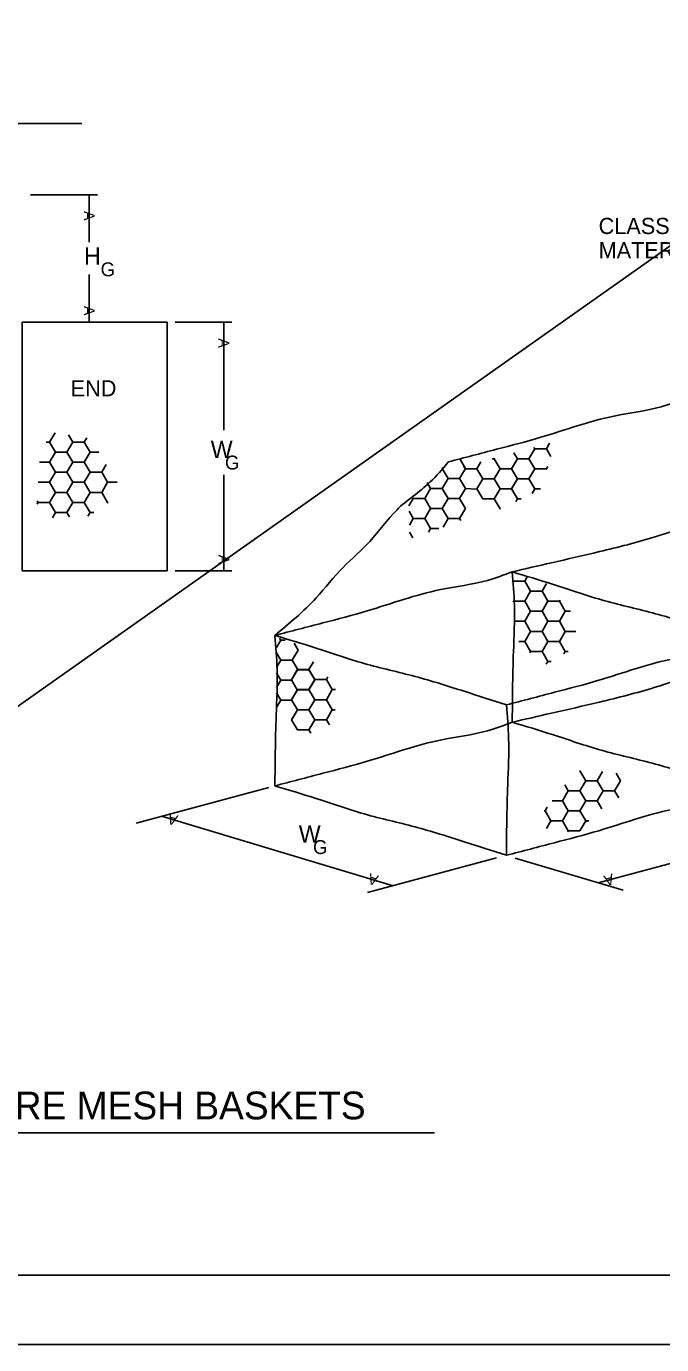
# Model space of a CAD drawing. Extents: x 3 to 3592, y -602 to 1171.
# Drawn here: x 2885 to 3022.2, y -601.8 to -317 of the extents above; entities that cross this region are included whole.
import ezdxf

# ---------------------------------------------------------------- set-up
doc = ezdxf.new("R2010")
doc.units = 0
for name, color, linetype in [('1', 7, 'Continuous'), ('2', 7, 'Continuous'), ('3', 7, 'Continuous')]:
    doc.layers.add(name, color=color, linetype=linetype)

msp = doc.modelspace()

# ---------------------------------------------------------------- linework, layer by layer
at = {"layer": '1'}
msp.add_line((2687.88, -601.81), (3528.88, -7.81), dxfattribs=at)
msp.add_lwpolyline([(2687.88, -7.81), (3528.88, -7.81), (3528.88, -601.81), (2687.88, -601.81)], close=True, dxfattribs=at)
msp.add_lwpolyline([(3512.88, -586.81), (3512.88, -22.81), (2726.88, -22.81), (2726.88, -586.81), (3512.88, -586.81), (3512.88, -560.45), (3312.88, -560.45), (3312.88, -495.77), (3512.88, -495.77), (3512.88, -466.81), (3312.88, -466.81), (3312.88, -586.81), (3391.68, -586.81), (3391.68, -560.45), (3391.68, -586.81), (3468.68, -586.81), (3468.68, -560.45), (3468.68, -572.77), (3512.88, -572.77)], dxfattribs=at)
at = {"layer": '2'}
for p, q in [((2885.86, -353.38), (2900.32, -353.38)), ((2898.57, -353.38), (2898.57, -363.63)), ((2898.57, -370.63), (2898.57, -380.88)), ((2913.61, -380.88), (2896.82, -380.88)), ((2917.11, -380.88), (2929.38, -380.88)), ((2927.63, -380.88), (2927.63, -404.26)), ((2927.63, -413.85), (2927.63, -434.63)), ((2979.76, -416.85), (2982.3, -416.95)), ((2917.11, -434.63), (2929.38, -434.63)), ((2989.96, -463.2), (2989.91, -467.34)), ((2937.38, -481.43), (2908.68, -489.13)), ((3069.4, -485.69), (3008.47, -502.03)), ((2948.9, -498.06), (2914.2, -487.65)), ((2964.2, -502.65), (2948.9, -498.06)), ((2986.53, -496.66), (2958.68, -504.13)), ((3013.87, -503.65), (2990.59, -496.67))]:
    msp.add_line(p, q, dxfattribs=at)
for points in [[(2915.36, -434.63), (2915.36, -380.88), (2884.11, -380.88), (2884.11, -434.63)], [(2893.75, -409.01), (2895, -406.84), (2897.5, -406.84), (2898.75, -409.01), (2897.5, -411.17), (2895, -411.17)], [(2890, -411.17), (2891.25, -409.01), (2893.75, -409.01), (2895, -411.17), (2893.75, -413.34), (2891.25, -413.34)], [(2893.75, -413.34), (2895, -411.17), (2897.5, -411.17), (2898.75, -413.34), (2897.5, -415.5), (2895, -415.5)], [(2986.05, -414.73), (2987.3, -412.57), (2989.8, -412.57), (2991.05, -414.73), (2989.8, -416.9), (2987.3, -416.9)], [(2989.8, -412.57), (2991.05, -410.4), (2993.55, -410.4), (2994.8, -412.57), (2993.55, -414.73), (2991.05, -414.73)], [(2890, -415.5), (2891.25, -413.34), (2893.75, -413.34), (2895, -415.5), (2893.75, -417.67), (2891.25, -417.67)], [(2893.75, -417.67), (2895, -415.5), (2897.5, -415.5), (2898.75, -417.67), (2897.5, -419.83), (2895, -419.83)], [(2897.5, -415.5), (2898.75, -413.34), (2901.25, -413.34), (2902.5, -415.5), (2901.25, -417.67), (2898.75, -417.67)], [(2974.81, -416.82), (2976.06, -414.65), (2978.56, -414.65), (2979.81, -416.82), (2978.56, -418.98), (2976.06, -418.98)], [(2982.3, -416.9), (2983.55, -414.73), (2986.05, -414.73), (2987.3, -416.9), (2986.05, -419.06), (2983.55, -419.06)], [(2890, -419.83), (2891.25, -417.67), (2893.75, -417.67), (2895, -419.83), (2893.75, -422), (2891.25, -422)], [(2992.64, -441.2), (2993.89, -439.04), (2996.39, -439.04), (2997.64, -441.2), (2996.39, -443.37), (2993.89, -443.37)], [(2992.64, -445.53), (2993.89, -443.37), (2996.39, -443.37), (2997.64, -445.53), (2996.39, -447.7), (2993.89, -447.7)], [(2996.39, -447.7), (2997.64, -445.53), (3000.14, -445.53), (3001.39, -447.7), (3000.14, -449.86), (2997.64, -449.86)], [(2942.26, -458.15), (2943.51, -455.99), (2946.01, -455.99), (2947.26, -458.15), (2946.01, -460.32), (2943.51, -460.32)], [(2942.28, -462.46), (2943.53, -460.29), (2946.03, -460.29), (2947.28, -462.46), (2946.03, -464.62), (2943.53, -464.62)], [(2942.28, -466.79), (2943.53, -464.62), (2946.03, -464.62), (2947.28, -466.79), (2946.03, -468.95), (2943.53, -468.95)], [(3004.55, -482.15), (3005.8, -479.98), (3008.3, -479.98), (3009.55, -482.15), (3008.3, -484.31), (3005.8, -484.31)], [(3000.79, -484.31), (3002.04, -482.15), (3004.54, -482.15), (3005.79, -484.31), (3004.54, -486.48), (3002.04, -486.48)]]:
    msp.add_lwpolyline(points, close=True, dxfattribs=at)
for points in [[(2889.25, -406.84), (2890, -406.84)], [(2890, -406.84), (2889.25, -406.84)], [(2891.17, -404.82), (2890, -406.84)], [(2890, -406.84), (2891.25, -409.01)], [(2895, -406.84), (2894.1, -405.27)], [(2897.5, -406.84), (2895, -406.84)], [(2898.06, -405.88), (2897.5, -406.84)], [(2998, -407.02), (2997.3, -408.24)], [(2997.3, -408.24), (2998, -407.02)], [(2891.25, -409.01), (2890, -411.17)], [(2897.5, -411.17), (2898.75, -409.01)], [(2898.75, -409.01), (2900.66, -409.01)], [(2991.05, -410.4), (2990.31, -409.12)], [(2990.31, -409.12), (2991.05, -410.4)], [(2994.8, -408.24), (2993.55, -410.4)], [(2993.55, -410.4), (2994.8, -408.24)], [(2994.63, -407.94), (2994.8, -408.24)], [(2994.8, -408.24), (2994.63, -407.94)], [(2994.8, -408.24), (2997.3, -408.24)], [(2997.3, -408.24), (2994.8, -408.24)], [(2997.3, -408.24), (2998.27, -409.92)], [(2998.27, -409.92), (2997.3, -408.24)], [(2890, -411.17), (2887.82, -411.17)], [(2887.82, -411.17), (2890, -411.17)], [(2890, -411.17), (2891.25, -413.34)], [(2898.75, -413.34), (2897.5, -411.17)], [(2902.24, -411.63), (2901.25, -413.34)], [(2901.25, -413.34), (2902.24, -411.63)], [(2974.73, -412.49), (2974.81, -412.49)], [(2974.81, -412.49), (2974.73, -412.49)], [(2974.91, -412.31), (2974.81, -412.49)], [(2974.81, -412.49), (2974.91, -412.31)], [(2974.81, -412.49), (2976.06, -414.65)], [(2976.06, -414.65), (2974.81, -412.49)], [(2979.81, -412.49), (2978.56, -414.65)], [(2978.61, -410.42), (2979.81, -412.49)], [(2979.8, -412.57), (2979.51, -412.07)], [(2982.3, -412.57), (2979.8, -412.57)], [(2983.16, -411.08), (2982.3, -412.57)], [(2982.3, -412.57), (2983.16, -411.08)], [(2983.55, -414.73), (2982.3, -412.57)], [(2986.05, -410.4), (2985.63, -410.4)], [(2985.63, -410.4), (2986.05, -410.4)], [(2986.13, -410.27), (2986.05, -410.4)], [(2986.05, -410.4), (2986.13, -410.27)], [(2987.3, -412.57), (2986.05, -410.4)], [(2986.05, -410.4), (2987.3, -412.57)], [(2987.3, -412.57), (2986.05, -414.73)], [(2989.8, -412.57), (2987.3, -412.57)], [(2991.05, -410.4), (2989.8, -412.57)], [(2993.55, -410.4), (2991.05, -410.4)], [(2994.8, -412.57), (2993.55, -410.4)], [(2993.55, -414.73), (2994.8, -412.57)], [(2997.3, -412.57), (2994.8, -412.57)], [(2994.8, -412.57), (2997.3, -412.57)], [(2997.59, -412.06), (2997.3, -412.57)], [(2997.3, -412.57), (2997.59, -412.06)], [(2997.38, -412.71), (2997.3, -412.57)], [(2997.3, -412.57), (2997.38, -412.71)], [(2890, -415.5), (2887.56, -415.5)], [(2887.56, -415.5), (2890, -415.5)], [(2891.25, -413.34), (2890, -415.5)], [(2890, -415.5), (2891.25, -417.67)], [(2901.25, -413.34), (2898.75, -413.34)], [(2902.5, -415.5), (2901.25, -413.34)], [(2901.25, -417.67), (2902.5, -415.5)], [(2902.5, -415.5), (2904.58, -415.5)], [(2904.58, -415.5), (2902.5, -415.5)], [(2972.31, -416.82), (2971.58, -415.56)], [(2971.58, -415.56), (2972.31, -416.82)], [(2976.06, -414.65), (2974.81, -416.82)], [(2978.56, -414.65), (2976.06, -414.65)], [(2986.05, -414.73), (2983.55, -414.73)], [(2989.8, -416.9), (2991.05, -414.73)], [(2991.05, -414.73), (2993.55, -414.73)], [(2994.8, -416.9), (2993.55, -414.73)], [(2993.55, -414.73), (2994.8, -416.9)], [(2891.25, -417.67), (2890, -419.83)], [(2897.5, -419.83), (2898.75, -417.67)], [(2898.75, -417.67), (2901.25, -417.67)], [(2902.5, -419.83), (2901.25, -417.67)], [(2901.25, -417.67), (2902.5, -419.83)], [(2972.31, -416.82), (2971.06, -418.98)], [(2974.81, -416.82), (2972.31, -416.82)], [(2986.05, -419.06), (2987.3, -416.9)], [(2987.3, -416.9), (2989.8, -416.9)], [(2991.05, -419.06), (2989.8, -416.9)], [(2989.8, -416.9), (2991.05, -419.06)], [(2994.8, -416.9), (2994.21, -417.92)], [(2994.21, -417.92), (2994.8, -416.9)], [(2996.06, -416.9), (2994.8, -416.9)], [(2994.8, -416.9), (2996.06, -416.9)], [(2887.27, -420.24), (2887.5, -419.83)], [(2887.5, -419.83), (2887.31, -419.5)], [(2890, -419.83), (2887.5, -419.83)], [(2887.5, -419.83), (2890, -419.83)], [(2890, -419.83), (2891.25, -422)], [(2893.75, -422), (2895, -419.83)], [(2895, -419.83), (2897.5, -419.83)], [(2898.75, -422), (2897.5, -419.83)], [(2897.5, -419.83), (2898.75, -422)], [(2902.5, -419.83), (2902.4, -420.02)], [(2902.4, -420.02), (2902.5, -419.83)], [(2902.66, -419.83), (2902.5, -419.83)], [(2902.5, -419.83), (2902.66, -419.83)], [(2967.63, -420.58), (2968.56, -418.98)], [(2968.56, -418.98), (2968.46, -418.82)], [(2968.56, -418.98), (2971.06, -418.98)], [(2971.06, -418.98), (2968.56, -418.98)], [(2971.06, -418.98), (2972.31, -421.15)], [(2972.31, -421.15), (2971.06, -423.31)], [(2971.06, -423.31), (2972.31, -421.15)], [(2972.31, -421.15), (2974.81, -421.15)], [(2974.81, -421.15), (2976.06, -418.98)], [(2974.81, -421.15), (2976.06, -423.31)], [(2976.06, -423.31), (2974.81, -421.15)], [(2976.06, -418.98), (2978.56, -418.98)], [(2978.56, -418.98), (2979.81, -421.15)], [(2979.81, -421.15), (2978.56, -423.31)], [(2987.3, -421.23), (2986.05, -419.06)], [(2987.26, -421.29), (2987.3, -421.23)], [(2987.3, -421.23), (2987.4, -421.23)], [(2987.4, -421.23), (2987.3, -421.23)], [(2991.05, -419.06), (2990.73, -419.61)], [(2991.86, -419.06), (2991.05, -419.06)], [(2891.25, -422), (2890.6, -423.14)], [(2890.6, -423.14), (2891.25, -422)], [(2891.25, -422), (2893.75, -422)], [(2894.33, -422.99), (2893.75, -422)], [(2893.75, -422), (2894.33, -422.99)], [(2898.75, -422), (2898.27, -422.84)], [(2898.27, -422.84), (2898.75, -422)], [(2899.59, -422), (2898.75, -422)], [(2898.75, -422), (2899.59, -422)], [(2967.66, -421.76), (2968.56, -423.31)], [(2968.56, -423.31), (2967.66, -421.76)], [(2968.56, -423.31), (2967.73, -424.75)], [(2967.73, -424.75), (2968.56, -423.31)], [(2968.56, -423.31), (2971.06, -423.31)], [(2971.06, -423.31), (2968.56, -423.31)], [(2971.06, -423.31), (2972.31, -425.48)], [(2972.31, -425.48), (2971.06, -423.31)], [(2976.06, -423.31), (2974.99, -425.16)], [(2974.99, -425.16), (2976.06, -423.31)], [(2976.06, -423.31), (2978.56, -423.31)], [(2978.56, -423.31), (2976.06, -423.31)], [(2978.56, -423.31), (2978.81, -423.76)], [(2967.76, -426.27), (2968.46, -427.48)], [(2968.46, -427.48), (2967.76, -426.27)], [(2972.31, -425.48), (2971.85, -426.28)], [(2971.85, -426.28), (2972.31, -425.48)], [(2972.31, -425.48), (2974.09, -425.48)], [(2974.09, -425.48), (2972.31, -425.48)], [(2989.97, -436.58), (2990.14, -436.87)], [(2990.14, -436.87), (2989.97, -436.58)], [(2990.14, -436.87), (2989.99, -437.14)], [(2989.99, -437.14), (2990.14, -436.87)], [(2990.14, -436.87), (2992.64, -436.87)], [(2992.64, -436.87), (2990.14, -436.87)], [(2993.17, -435.95), (2992.64, -436.87)], [(2992.64, -436.87), (2993.17, -435.95)], [(2992.64, -436.87), (2993.89, -439.04)], [(2993.89, -439.04), (2992.64, -436.87)], [(2997.36, -437.36), (2996.39, -439.04)], [(2990.14, -441.2), (2990.13, -441.18)], [(2990.13, -441.18), (2990.14, -441.2)], [(2990.14, -441.2), (2990.13, -441.22)], [(2992.64, -441.2), (2990.14, -441.2)], [(2993.89, -439.04), (2992.64, -441.2)], [(2996.39, -439.04), (2993.89, -439.04)], [(2996.39, -443.37), (2997.64, -441.2)], [(2997.64, -441.2), (2996.81, -439.76)], [(3000.14, -441.2), (2997.64, -441.2)], [(2997.64, -441.2), (3000.14, -441.2)], [(3000.29, -440.94), (3000.14, -441.2)], [(3000.14, -441.2), (3000.29, -440.94)], [(3001.39, -443.37), (3000.14, -441.2)], [(3000.14, -441.2), (3001.39, -443.37)], [(2997.64, -445.53), (2996.39, -443.37)], [(3001.39, -443.37), (3000.14, -445.53)], [(3002.51, -443.37), (3001.39, -443.37)], [(2990.28, -445.53), (2992.64, -445.53)], [(2992.64, -445.53), (2993.89, -447.7)], [(3000.14, -445.53), (2997.64, -445.53)], [(2939.93, -449.59), (2939.01, -451.19)], [(2939.01, -451.19), (2939.93, -449.59)], [(2939.69, -449.18), (2939.93, -449.59)], [(2939.93, -449.59), (2939.69, -449.18)], [(2939.93, -449.59), (2940.87, -449.59)], [(2940.87, -449.59), (2939.93, -449.59)], [(2991.38, -449.86), (2992.64, -449.86)], [(2992.64, -449.86), (2991.38, -449.86)], [(2993.89, -447.7), (2992.64, -449.86)], [(2992.64, -449.86), (2993.89, -447.7)], [(2992.64, -449.86), (2993.89, -452.03)], [(2993.89, -452.03), (2992.64, -449.86)], [(2993.89, -447.7), (2996.39, -447.7)], [(2996.39, -447.7), (2997.64, -449.86)], [(2997.64, -449.86), (2996.39, -452.03)], [(2996.39, -452.03), (2997.64, -449.86)], [(2997.64, -449.86), (3000.14, -449.86)], [(3000.14, -449.86), (3001.39, -447.7)], [(3001.39, -452.03), (3000.14, -449.86)], [(3000.14, -449.86), (3001.39, -452.03)], [(3001.39, -447.7), (3003.64, -447.7)], [(2939.01, -452.33), (2939.93, -453.92)], [(2939.93, -453.92), (2939.01, -452.33)], [(2943.68, -451.76), (2942.43, -453.92)], [(2942.83, -450.28), (2943.68, -451.76)], [(2993.89, -452.03), (2993.72, -452.31)], [(2993.72, -452.31), (2993.89, -452.03)], [(2993.89, -452.03), (2996.39, -452.03)], [(2996.39, -452.03), (2993.89, -452.03)], [(2996.39, -452.03), (2997.2, -453.43)], [(2997.64, -454.19), (2996.39, -452.03)], [(3001.39, -452.03), (3001.07, -452.59)], [(3001.07, -452.59), (3001.39, -452.03)], [(3002.02, -452.03), (3001.39, -452.03)], [(3001.39, -452.03), (3002.02, -452.03)], [(2939.93, -453.92), (2939.01, -455.52)], [(2939.01, -455.52), (2939.93, -453.92)], [(2939.93, -453.92), (2942.43, -453.92)], [(2942.43, -453.92), (2939.93, -453.92)], [(2942.42, -453.92), (2942.99, -452.94)], [(2943.67, -456.08), (2942.42, -453.92)], [(2947, -454.27), (2946.03, -455.96)], [(2946.03, -455.96), (2947, -454.27)], [(2997.29, -454.81), (2997.64, -454.19)], [(2998.34, -454.19), (2997.64, -454.19)], [(2997.64, -454.19), (2998.34, -454.19)], [(2939.01, -456.66), (2939.27, -457.11)], [(2939.93, -458.25), (2939.01, -456.66)], [(2939.93, -458.25), (2939.01, -459.85)], [(2939.01, -459.85), (2939.93, -458.25)], [(2939.93, -458.25), (2942.43, -458.25)], [(2942.43, -458.25), (2939.93, -458.25)], [(2943.52, -455.98), (2942.27, -458.15)], [(2946.03, -455.96), (2943.53, -455.96)], [(2947.28, -458.13), (2946.03, -455.96)], [(2946.03, -460.29), (2947.28, -458.13)], [(2949.78, -458.13), (2947.28, -458.13)], [(2947.28, -458.13), (2949.78, -458.13)], [(2950.13, -457.52), (2949.78, -458.13)], [(2949.78, -458.13), (2950.13, -457.52)], [(2951.03, -460.29), (2949.78, -458.13)], [(2949.78, -458.13), (2951.03, -460.29)], [(2939.93, -462.58), (2939.01, -460.99)], [(2943.52, -460.31), (2942.27, -462.48)], [(2947.28, -462.46), (2946.03, -460.29)], [(2951.03, -460.29), (2949.78, -462.46)], [(2949.78, -462.46), (2951.03, -460.29)], [(2951.76, -460.29), (2951.03, -460.29)], [(2951.03, -460.29), (2951.76, -460.29)], [(2939.01, -464.18), (2939.93, -462.58)], [(2939.93, -462.58), (2942.43, -462.58)], [(2942.27, -462.48), (2943.52, -464.64)], [(2949.78, -462.46), (2947.28, -462.46)], [(2951.03, -464.62), (2949.78, -462.46)], [(2943.52, -464.64), (2942.3, -466.76)], [(2946.03, -468.95), (2947.28, -466.79)], [(2947.28, -466.79), (2949.78, -466.79)], [(2949.78, -466.79), (2951.03, -464.62)], [(2949.78, -466.79), (2950.43, -467.92)], [(2950.43, -467.92), (2949.78, -466.79)], [(2951.03, -464.62), (2951.68, -464.62)], [(2951.68, -464.62), (2951.03, -464.62)], [(2943.53, -468.95), (2946.03, -468.95)], [(2946.46, -469.71), (2946.03, -468.95)], [(2946.03, -468.95), (2946.46, -469.71)], [(3004.5, -477.82), (3004.54, -477.82)], [(3004.54, -477.82), (3004.5, -477.82)], [(3004.57, -477.76), (3004.54, -477.82)], [(3004.54, -477.82), (3005.79, -479.98)], [(3009.46, -477.99), (3008.3, -479.98)], [(3008.3, -479.98), (3009.46, -477.99)], [(3013.3, -479.98), (3012.36, -478.35)], [(3012.36, -478.35), (3013.3, -479.98)], [(3002.04, -482.15), (3001.31, -480.89)], [(3005.79, -479.98), (3004.54, -482.15)], [(3005.8, -479.98), (3004.99, -478.57)], [(3008.3, -479.98), (3005.8, -479.98)], [(3009.55, -482.15), (3008.3, -479.98)], [(3013.3, -479.98), (3012.05, -482.15)], [(3012.05, -482.15), (3013.3, -479.98)], [(3013.41, -479.98), (3013.3, -479.98)], [(3013.3, -479.98), (3013.41, -479.98)], [(3004.54, -482.15), (3002.04, -482.15)], [(3012.05, -482.15), (3009.55, -482.15)], [(3012.92, -483.64), (3012.05, -482.15)], [(2996.86, -486.48), (2997.04, -486.48)], [(2997.04, -486.48), (2996.86, -486.48)], [(2997.51, -485.66), (2997.04, -486.48)], [(2997.04, -486.48), (2997.51, -485.66)], [(2997.04, -486.48), (2998.29, -488.64)], [(2998.29, -488.64), (2997.04, -486.48)], [(2998.58, -484.31), (3000.79, -484.31)], [(3000.79, -484.31), (3002.04, -486.48)], [(3002.04, -486.48), (3000.79, -488.64)], [(3000.79, -488.64), (3002.04, -486.48)], [(3002.04, -486.48), (3004.54, -486.48)], [(3004.54, -486.48), (3005.79, -488.64)], [(3004.55, -486.48), (3005.8, -484.31)], [(3005.8, -488.64), (3004.55, -486.48)], [(3005.8, -484.31), (3008.3, -484.31)], [(3008.3, -484.31), (3009.29, -486.02)], [(2998.29, -488.64), (2997.32, -490.32)], [(2997.32, -490.32), (2998.29, -488.64)], [(2998.29, -488.64), (3000.79, -488.64)], [(3000.79, -488.64), (2998.29, -488.64)], [(3000.79, -488.64), (3002.04, -490.81)], [(3002.04, -490.81), (3000.79, -488.64)], [(3005.79, -488.64), (3004.54, -490.81)], [(3004.55, -490.81), (3005.8, -488.64)], [(3005.97, -488.96), (3005.79, -488.64)], [(3006.47, -488.64), (3005.8, -488.64)], [(3005.8, -488.64), (3006.47, -488.64)], [(3002.04, -490.81), (3001.94, -490.98)], [(3001.94, -490.98), (3002.04, -490.81)], [(3002.04, -490.81), (3004.54, -490.81)], [(3003.05, -490.81), (3002.04, -490.81)]]:
    msp.add_lwpolyline(points, dxfattribs=at)
for points in [[(3027.41, -397.34), (3022.1, -399.18), (3011.91, -401.18), (2996.13, -405.77), (2986.53, -408.37), (2976.16, -411.09)], [(2976.16, -411.09), (2972.16, -415.49), (2964.97, -421.48), (2959.17, -428.28), (2953.38, -433.87), (2947.58, -440.47), (2938.66, -448.59)], [(3041.16, -421.09), (3029.37, -424.49), (3020.77, -427.29), (3008.78, -430.48), (2998.39, -432.88), (2989.91, -434.84)], [(2989.91, -434.84), (2984.6, -436.68), (2974.41, -438.68), (2958.63, -443.27), (2949.03, -445.87), (2938.66, -448.59)], [(2989.91, -434.84), (2998.63, -437.51), (3009.22, -440.9), (3020.21, -443.7), (3030.8, -446.9), (3039.91, -449.84)], [(2989.91, -434.84), (2990.4, -442.09), (2990.2, -452.08), (2990, -460.08), (2989.96, -463.2)], [(2938.66, -448.59), (2947.38, -451.26), (2957.97, -454.65), (2968.96, -457.45), (2979.55, -460.65), (2988.66, -463.59)], [(2938.66, -448.59), (2939.15, -455.84), (2938.95, -465.83), (2938.75, -473.83), (2938.66, -481.09)], [(3039.91, -449.84), (3034.6, -451.68), (3024.41, -453.68), (3008.63, -458.27), (2999.03, -460.87), (2988.66, -463.59)], [(3041.16, -453.59), (3029.37, -456.99), (3020.77, -459.79), (3008.78, -462.98), (2998.39, -465.38), (2989.91, -467.34)], [(2988.66, -463.59), (2989.15, -470.84), (2988.95, -480.83), (2988.75, -488.83), (2988.66, -496.09)], [(2989.91, -467.34), (2984.6, -469.18), (2974.41, -471.18), (2958.63, -475.77), (2949.03, -478.37), (2938.66, -481.09)], [(2989.91, -467.34), (2998.63, -470.01), (3009.22, -473.4), (3020.21, -476.2), (3030.8, -479.4), (3039.91, -482.34)], [(2938.66, -481.09), (2947.38, -483.76), (2957.97, -487.15), (2968.96, -489.95), (2979.55, -493.15), (2988.66, -496.09)], [(3039.91, -482.34), (3034.6, -484.18), (3024.41, -486.18), (3008.63, -490.77), (2999.03, -493.37), (2988.66, -496.09)]]:
    msp.add_spline(points, degree=3, dxfattribs=at)
at = {"layer": '3'}
for p, q in [((2812.14, -337.97), (2896.98, -337.97)), ((2870.43, -556.08), (2973.12, -556.08))]:
    msp.add_line(p, q, dxfattribs=at)

# ---------------------------------------------------------------- texts
at = {"layer": '2'}
for rotation, p in [(270, (2897.41, -356.88)), (270, (2897.41, -377.38)), (270, (2926.46, -384.38)), (270, (2926.46, -431.13)), (163.3008, (2917.89, -487.54)), (163.3008, (2961.19, -500.53)), (195.0184, (3011.55, -500))]:
    msp.add_text('A', height=2.33, rotation=rotation, dxfattribs=at).set_placement(p)
at = {"layer": '3'}
for s, height, p in [('CLASS 2, TYPE B GEOTEXTILE', 3.5, (3008.59, -361.86)), ('MATERIAL, SEE NOTES 7 AND 8.', 3.5, (3008.59, -367.11)), ('H', 3.75, (2897.43, -368.47)), ('G', 3, (2901.02, -370.98)), ('END', 3.5, (2894.55, -396.93)), ('W', 3.75, (2924.8, -410.28)), ('G', 3, (2927.88, -412.73)), ('W', 3.75, (2943.82, -493.35)), ('G', 3, (2946.9, -495.81)), ('WIRE MESH BASKETS', 6, (2872.67, -553.13))]:
    msp.add_text(s, height=height, dxfattribs=at).set_placement(p)

doc.saveas('drawing.dxf')
